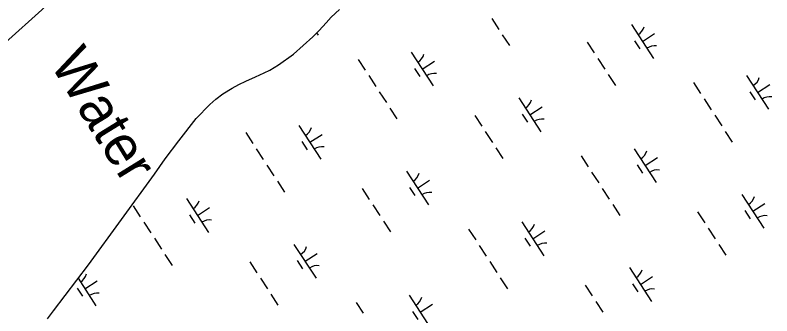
# Model space of a CAD drawing. Extents: x 3953924 to 3974542, y 193747 to 216192.
# Drawn here: x 3961392 to 3962330, y 204790 to 205163 of the extents above; entities that cross this region are included whole.
import ezdxf

# ---------------------------------------------------------------- set-up
doc = ezdxf.new("R2010")
doc.units = 0
for name, color, linetype in [('V-RIVR-IDEN', 7, 'Continuous'), ('V-TOPO-SHOR', 7, 'Continuous'), ('V-WETL-SWMP', 7, 'Continuous')]:
    doc.layers.add(name, color=color, linetype=linetype)

msp = doc.modelspace()

# ---------------------------------------------------------------- linework, layer by layer
at = {"layer": 'V-TOPO-SHOR'}
for points in [[(3961379.83, 205128.87), (3961425.01, 205169.16), (3961439.49, 205183.74), (3961449.35, 205194.27)], [(3961432.08, 204786.62), (3961439.27, 204796.41), (3961482.7, 204853.49), (3961564.69, 204965.77), (3961577.93, 204984.72), (3961594.77, 205006.96), (3961616.22, 205034.42), (3961633.02, 205052.08), (3961640.59, 205058.68), (3961649.17, 205065.14), (3961660.82, 205072.23), (3961669.01, 205076.78), (3961677.96, 205080.95), (3961689.86, 205086.12), (3961700.73, 205091.04), (3961707.52, 205094.58), (3961718.27, 205100.91), (3961736.84, 205114.21), (3961760.81, 205135.92), (3961768.89, 205143.79), (3961777.49, 205153.19), (3961783.78, 205160.18), (3961793.79, 205169.82)]]:
    msp.add_lwpolyline(points, dxfattribs=at)
at = {"layer": 'V-WETL-SWMP'}
for p, q in [((3961425.01, 205169.16), (3961379.83, 205128.87)), ((3961783.78, 205160.18), (3961793.79, 205169.83)), ((3961777.49, 205153.19), (3961783.78, 205160.18)), ((3961982.71, 205158.38), (3961991.44, 205144.97)), ((3961768.9, 205143.79), (3961777.49, 205153.19)), ((3962155.76, 205150.93), (3962183.04, 205109.02)), ((3961736.84, 205114.21), (3961760.81, 205135.92)), ((3961760.81, 205135.92), (3961768.9, 205143.79)), ((3961765.57, 205140.55), (3961767.32, 205137.85)), ((3961995.8, 205138.27), (3962004.53, 205124.86)), ((3962169.4, 205129.97), (3962184.49, 205139.79)), ((3962101.01, 205129.25), (3962109.74, 205115.84)), ((3962159.66, 205130.79), (3962166.21, 205120.74)), ((3961882.94, 205116.8), (3961910.21, 205074.89)), ((3961718.27, 205100.91), (3961736.84, 205114.21)), ((3961817.12, 205107.87), (3961825.85, 205094.46)), ((3962114.1, 205109.13), (3962122.83, 205095.72)), ((3961707.52, 205094.58), (3961718.27, 205100.91)), ((3961896.58, 205095.85), (3961911.66, 205105.67)), ((3961689.86, 205086.12), (3961700.73, 205091.04)), ((3961700.73, 205091.04), (3961707.52, 205094.58)), ((3961886.84, 205096.66), (3961893.38, 205086.61)), ((3962127.19, 205089.02), (3962135.92, 205075.61)), ((3961669.01, 205076.78), (3961677.96, 205080.95)), ((3961677.96, 205080.95), (3961689.86, 205086.12)), ((3961830.21, 205087.75), (3961838.94, 205074.34)), ((3962232.83, 205079.03), (3962241.56, 205065.63)), ((3962298.65, 205087.97), (3962325.93, 205046.06)), ((3961649.17, 205065.14), (3961660.82, 205072.23)), ((3961660.82, 205072.23), (3961669.01, 205076.78)), ((3962312.29, 205067.01), (3962327.38, 205076.83)), ((3961640.59, 205058.68), (3961649.17, 205065.14)), ((3961843.3, 205067.64), (3961852.03, 205054.23)), ((3962016.36, 205060.18), (3962043.64, 205018.28)), ((3962302.55, 205067.83), (3962309.1, 205057.78)), ((3961616.22, 205034.42), (3961633.02, 205052.08)), ((3961633.02, 205052.08), (3961640.59, 205058.68)), ((3962245.93, 205058.92), (3962254.65, 205045.51)), ((3961856.4, 205047.52), (3961865.13, 205034.11)), ((3962030, 205039.23), (3962045.08, 205049.05)), ((3961594.76, 205006.96), (3961616.22, 205034.42)), ((3961961.6, 205038.5), (3961970.33, 205025.09)), ((3962020.26, 205040.05), (3962026.8, 205029.99)), ((3962259.02, 205038.81), (3962267.75, 205025.4)), ((3961743.53, 205026.05), (3961770.81, 204984.15)), ((3961677.71, 205017.12), (3961686.44, 205003.71)), ((3961757.17, 205005.1), (3961772.26, 205014.92)), ((3961974.7, 205018.39), (3961983.42, 205004.98)), ((3962272.11, 205018.69), (3962280.84, 205005.28)), ((3961577.93, 204984.72), (3961594.76, 205006.96)), ((3961747.43, 205005.92), (3961753.98, 204995.86)), ((3961690.81, 204997.01), (3961699.53, 204983.6)), ((3961987.79, 204998.28), (3961996.52, 204984.87)), ((3962159.25, 204997.22), (3962186.53, 204955.32)), ((3962093.43, 204988.29), (3962102.16, 204974.88)), ((3962172.89, 204976.27), (3962187.97, 204986.09)), ((3961564.69, 204965.77), (3961577.93, 204984.72)), ((3961703.9, 204976.89), (3961712.63, 204963.48)), ((3962163.15, 204977.09), (3962169.69, 204967.03)), ((3961876.95, 204969.44), (3961904.23, 204927.53)), ((3962106.52, 204968.18), (3962115.25, 204954.77)), ((3961482.7, 204853.49), (3961564.69, 204965.77)), ((3961890.59, 204948.48), (3961905.68, 204958.3)), ((3961716.99, 204956.78), (3961725.72, 204943.37)), ((3961822.2, 204947.76), (3961830.93, 204934.35)), ((3961880.85, 204949.3), (3961887.4, 204939.25)), ((3962119.61, 204948.06), (3962128.34, 204934.65)), ((3962292.67, 204940.61), (3962319.95, 204898.7)), ((3961604.13, 204935.31), (3961631.41, 204893.4)), ((3962306.31, 204919.65), (3962321.39, 204929.47)), ((3961538.31, 204926.38), (3961547.04, 204912.97)), ((3961617.77, 204914.36), (3961632.85, 204924.18)), ((3961835.29, 204927.65), (3961844.02, 204914.24)), ((3962132.71, 204927.95), (3962141.44, 204914.54)), ((3962296.57, 204920.47), (3962303.11, 204910.42)), ((3961608.03, 204915.18), (3961614.57, 204905.12)), ((3962237.91, 204918.93), (3962246.64, 204905.52)), ((3961551.4, 204906.26), (3961560.13, 204892.85)), ((3961848.38, 204907.53), (3961857.11, 204894.12)), ((3962019.84, 204906.48), (3962047.12, 204864.57)), ((3961954.02, 204897.55), (3961962.75, 204884.14)), ((3962033.48, 204885.53), (3962048.57, 204895.35)), ((3962251.01, 204898.81), (3962259.74, 204885.4)), ((3961564.49, 204886.15), (3961573.22, 204872.74)), ((3962023.74, 204886.34), (3962030.29, 204876.29)), ((3961737.55, 204878.69), (3961764.83, 204836.79)), ((3961967.12, 204877.43), (3961975.85, 204864.02)), ((3962264.1, 204878.7), (3962272.83, 204865.29)), ((3961577.59, 204866.03), (3961586.32, 204852.62)), ((3961751.19, 204857.74), (3961766.27, 204867.56)), ((3961682.79, 204857.01), (3961691.52, 204843.61)), ((3961741.45, 204858.56), (3961748, 204848.5)), ((3961980.21, 204857.32), (3961988.94, 204843.91)), ((3961439.27, 204796.41), (3961482.7, 204853.49)), ((3962153.26, 204849.86), (3962180.54, 204807.96)), ((3961469.88, 204836.64), (3961492, 204802.66)), ((3961695.89, 204836.9), (3961704.62, 204823.49)), ((3961993.3, 204837.2), (3962002.03, 204823.79)), ((3962166.9, 204828.91), (3962181.99, 204838.73)), ((3961478.36, 204823.61), (3961493.45, 204833.43)), ((3962098.51, 204828.18), (3962107.24, 204814.77)), ((3962157.16, 204829.73), (3962163.71, 204819.67)), ((3961468.62, 204824.43), (3961475.17, 204814.37)), ((3961708.98, 204816.79), (3961717.71, 204803.38)), ((3961814.62, 204806.8), (3961823.35, 204793.39)), ((3961880.44, 204815.73), (3961907.72, 204773.83)), ((3962111.6, 204808.07), (3962120.33, 204794.66)), ((3961894.08, 204794.78), (3961909.16, 204804.6)), ((3961432.08, 204786.62), (3961439.27, 204796.41)), ((3961884.34, 204795.6), (3961890.89, 204785.54))]:
    msp.add_line(p, q, dxfattribs=at)
for centre, start, end in [((3962154.53, 205153.25), 302.29009, 343.83375), ((3962184.67, 205106.95), 82.29009, 123.83375), ((3961881.71, 205119.12), 302.29009, 343.83375), ((3961911.84, 205072.83), 82.29009, 123.83375), ((3962297.42, 205090.29), 302.29009, 343.83375), ((3962327.56, 205044), 82.29009, 123.83375), ((3962015.13, 205062.51), 302.29009, 343.83375), ((3962045.26, 205016.21), 82.29009, 123.83375), ((3961742.3, 205028.38), 302.29009, 343.83375), ((3961772.44, 204982.08), 82.29009, 123.83375), ((3962158.02, 204999.55), 302.29009, 343.83375), ((3961875.72, 204971.76), 302.29009, 343.83375), ((3962188.15, 204953.25), 82.29009, 123.83375), ((3961905.86, 204925.47), 82.29009, 123.83375), ((3961602.9, 204937.63), 302.29009, 343.83375), ((3962291.44, 204942.93), 302.29009, 343.83375), ((3962321.58, 204896.63), 82.29009, 123.83375), ((3961633.03, 204891.34), 82.29009, 123.83375), ((3962018.61, 204908.8), 302.29009, 343.83375), ((3961736.32, 204881.02), 302.29009, 343.83375), ((3962048.75, 204862.51), 82.29009, 123.83375), ((3961766.46, 204834.72), 82.29009, 123.83375), ((3962152.03, 204852.19), 302.29009, 343.83375), ((3961463.49, 204846.89), 302.29009, 343.83375), ((3961493.63, 204800.59), 82.29009, 123.83375), ((3962182.17, 204805.89), 82.29009, 123.83375), ((3961879.21, 204818.06), 302.29009, 343.83375)]:
    msp.add_arc(centre, 17.62, start, end, dxfattribs=at)

# ---------------------------------------------------------------- texts
at = {"layer": 'V-RIVR-IDEN'}
msp.add_text('Water', height=50, rotation=301.66125, dxfattribs=at).set_placement((3961434.14, 205102.83))

doc.saveas('drawing.dxf')
